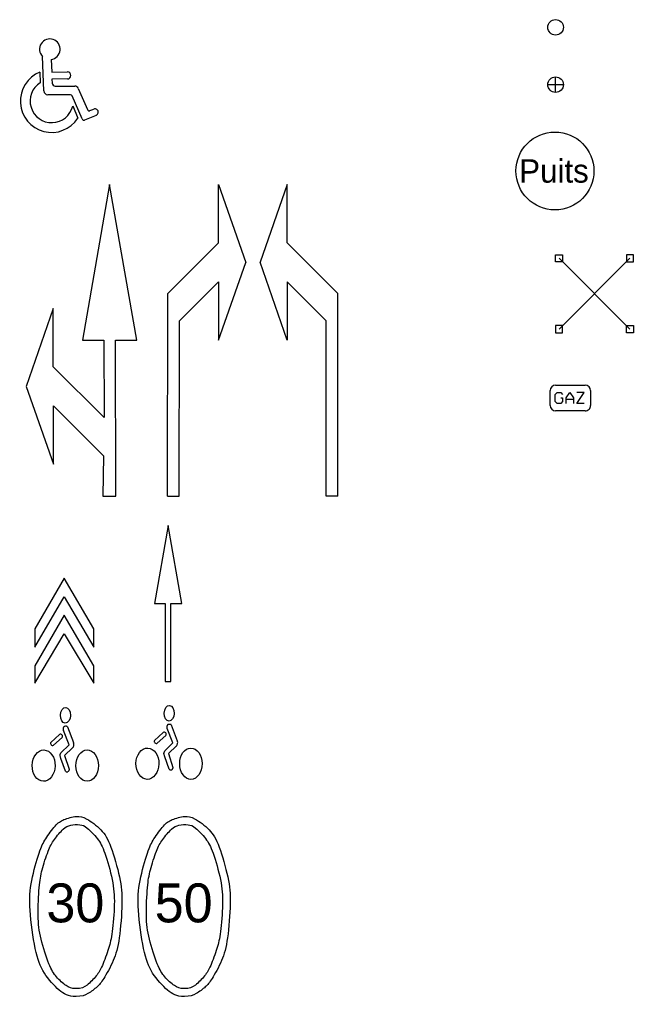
# Model space of a CAD drawing. Extents: x -1.5 to 18.2, y -66.6 to 3.3.
# Drawn here: x 7.93 to 15.81, y -64.82 to -52.28 of the extents above; entities that cross this region are included whole.
import ezdxf

# ---------------------------------------------------------------- set-up
doc = ezdxf.new("R2010")
doc.units = 0
for name, color, linetype in [('SOL_AFFLEUREMENT', 7, 'Continuous'), ('SOL_ELEC_POTEAU', 7, 'Continuous'), ('SOL_MOBILIER_DIVERS', 7, 'Continuous'), ('SOL_PLAQUE_GAZ', 7, 'Continuous'), ('SOL_SIGNALISATION_HORIZONTALE', 7, 'Continuous'), ('SOL_SIGNALISATION_VERTICALE', 7, 'Continuous')]:
    doc.layers.add(name, color=color, linetype=linetype)

# ---------------------------------------------------------------- blocks, each defined once
blk = doc.blocks.new('SYMBOLE_PMR')
for p, q in [((-0.048, 0.492), (-0.065, 0.934)), ((0.047, 0.896), (0.053, 0.734)), ((-0.099, 0.735), (-0.093, 0.598)), ((0.053, 0.734), (0.254, 0.736)), ((0.255, 0.646), (0.057, 0.644)), ((0.057, 0.644), (0.059, 0.593)), ((0.099, 0.554), (0.349, 0.554)), ((0.395, 0.524), (0.511, 0.252)), ((0.293, 0.444), (0.002, 0.444)), ((0.443, 0.132), (0.316, 0.429)), ((0.323, 0.299), (0.39, 0.143)), ((0.543, 0.239), (0.592, 0.258)), ((0.624, 0.179), (0.475, 0.119))]:
    blk.add_line(p, q)
for centre, radius, start, end in [((0.029, 1.028), 0.132, 277.5864, 224.7546), ((0.053, 0.362), 0.402, 112.1232, 326.8956), ((0.254, 0.691), 0.045, 270.3, 90.3), ((0.053, 0.362), 0.277, 121.8325, 346.8056), ((0.099, 0.594), 0.04, 182.1973, 270), ((0.349, 0.504), 0.05, 23.1986, 90), ((0.002, 0.494), 0.05, 182.1973, 270), ((0.293, 0.419), 0.025, 23.1986, 90), ((0.534, 0.262), 0.025, 203.1986, 291.9218), ((0.608, 0.219), 0.0428, 291.9212, 111.9218), ((0.466, 0.142), 0.025, 203.1986, 291.9218)]:
    blk.add_arc(centre, radius, start, end)
blk = doc.blocks.new('REPERE_ARCHEOLOGIQUE')
blk.add_circle((0, 0), 0.1)
blk = doc.blocks.new('CLOU_DE_CHAUSSEE')
for p, q in [((-0.1, 0), (0.1, 0)), ((0, -0.1), (0, 0.1))]:
    blk.add_line(p, q)
blk.add_circle((0, 0), 0.1)
blk = doc.blocks.new('PYLONE_ELECTRIQUE')
for points in [[(0, 1), (0.091, 1), (0.091, 0.909), (0, 0.909)], [(0.909, 0.909), (1, 0.909), (1, 1), (0.909, 1)], [(0.091, 0.091), (0, 0.091), (0, 0), (0.091, 0)], [(0.909, 0.091), (1, 0.091), (1, 0), (0.909, 0)]]:
    blk.add_lwpolyline(points, close=True)
for points in [[(0.955, 0.045), (0.045, 0.955)], [(0.045, 0.045), (0.955, 0.955)]]:
    blk.add_lwpolyline(points)
blk = doc.blocks.new('PLAQUE_GAZ')
for p, q in [((-0.07, 0.07), (-0.07, 0.26)), ((0, 0.33), (0.38, 0.33)), ((0.45, 0.26), (0.45, 0.07)), ((0.38, 0), (0, 0))]:
    blk.add_line(p, q)
for points in [[(0.068, 0.166), (0.091, 0.166), (0.091, 0.119), (0.068, 0.095), (0.021, 0.095), (-0.003, 0.119), (-0.003, 0.211), (0.021, 0.234), (0.068, 0.234), (0.091, 0.211)], [(0.136, 0.095), (0.136, 0.166), (0.183, 0.234), (0.23, 0.166), (0.23, 0.095)], [(0.23, 0.143), (0.136, 0.143)], [(0.369, 0.095), (0.275, 0.095), (0.369, 0.234), (0.275, 0.234)]]:
    blk.add_lwpolyline(points)
for centre, start, end in [((0, 0.26), 90, 180), ((0.38, 0.26), 0.0424, 90), ((0, 0.07), 180.0424, 270), ((0.38, 0.07), 270, 0.0424)]:
    blk.add_arc(centre, 0.07, start, end)
blk = doc.blocks.new('PUITS')
blk.add_circle((0, 0), 0.5)
blk.add_text('Puits', height=0.3).set_placement((-0.458, -0.15))
blk = doc.blocks.new('SYMBOLE_FLECHE_DROIT_GAUCHE')
for p, q in [((0, 4), (-0.346, 1.999)), ((0.354, 2.001), (0, 4)), ((-0.722, 2.409), (-1.069, 1.408)), ((-0.72, 1.659), (-0.722, 2.409)), ((-0.346, 1.999), (-0.071, 2)), ((-0.071, 2), (-0.069, 1.01)), ((0.079, 2), (0.354, 2.001)), ((0.084, 0), (0.079, 2)), ((-0.069, 1.01), (-0.72, 1.659)), ((-1.069, 1.408), (-0.717, 0.409)), ((-0.717, 0.409), (-0.719, 1.159)), ((-0.719, 1.159), (-0.076, 0.518)), ((-0.076, 0.518), (-0.084, 0)), ((-0.084, 0), (0.084, 0))]:
    blk.add_line(p, q)
blk = doc.blocks.new('SYMBOLE_FLECHE_DROITE')
for p, q in [((0.579, 3.249), (0.58, 3.999)), ((0.58, 3.999), (0.929, 2.999)), ((-0.072, 2.6), (0.579, 3.249)), ((0.577, 1.999), (0.929, 2.999)), ((0.078, 2.25), (0.578, 2.749)), ((0.578, 2.749), (0.577, 1.999)), ((-0.075, 0), (-0.072, 2.6)), ((0.075, 0), (0.078, 2.25)), ((-0.075, 0), (0.075, 0))]:
    blk.add_line(p, q)
blk = doc.blocks.new('SYMBOLE_FLECHE_GAUCHE')
for p, q in [((-0.575, 4), (-0.925, 3)), ((-0.575, 3.25), (-0.575, 4)), ((0.075, 2.6), (-0.575, 3.25)), ((-0.575, 2), (-0.925, 3)), ((-0.075, 2.25), (-0.575, 2.75)), ((-0.575, 2.75), (-0.575, 2)), ((0.075, 0), (0.075, 2.6)), ((-0.075, 0), (-0.075, 2.25)), ((0.075, 0), (-0.075, 0))]:
    blk.add_line(p, q)
blk = doc.blocks.new('SYMBOLE_VELO_CHEVRON')
for p, q in [((-0.016, 2.103), (-0.396, 1.453)), ((0.364, 1.453), (-0.016, 2.103)), ((-0.396, 1.215), (-0.016, 1.865)), ((-0.016, 1.865), (0.364, 1.215)), ((-0.016, 1.628), (-0.396, 0.978)), ((0.364, 0.978), (-0.016, 1.628)), ((-0.396, 1.453), (-0.396, 1.215)), ((-0.396, 0.753), (-0.016, 1.39)), ((-0.016, 1.39), (0.364, 0.753)), ((0.364, 1.215), (0.364, 1.453)), ((-0.396, 0.978), (-0.396, 0.753)), ((0.364, 0.753), (0.364, 0.978)), ((0.021, 0.198), (0.024, 0.196)), ((0.047, -0.351), (0.047, -0.355)), ((0.047, -0.355), (0.047, -0.359))]:
    blk.add_line(p, q)
for points in [[(-0.059, -0.139), (0.047, -0.036), (-0.028, 0.149)], [(0.024, 0.196), (0.102, -0.009)], [(-0.079, 0.097), (-0.189, -0.005)], [(-0.154, -0.04), (-0.043, 0.058)], [(0.091, -0.076), (-0.012, -0.174), (0.047, -0.351)], [(-0.059, -0.214), (-0.071, -0.172), (-0.067, -0.159), (-0.059, -0.139)], [(0, -0.375), (-0.059, -0.214)]]:
    blk.add_lwpolyline(points)
for centre, radius, start, end in [((-0.007, 0.173), 0.0247, 156.3706, 174.6855), ((0.051, 0.168), 0.0823, 174.6855, 186.3402), ((0.002, 0.163), 0.0335, 186.3402, 204.655), ((0.006, 0.168), 0.0381, 141.6325, 156.3706), ((-0.003, 0.175), 0.0275, 123.6901, 141.6325), ((-0.01, 0.186), 0.0139, 98.3659, 123.6901), ((0.006, 0.082), 0.119, 87.151, 98.5527), ((0.011, 0.178), 0.0229, 62.3852, 87.7094), ((-0.066, 0.073), 0.0272, 325.3489, 120.0699), ((-0.168, -0.019), 0.0253, 146.5278, 303.4722), ((0.059, -0.039), 0.0469, 330.8025, 345.3791), ((0.032, -0.045), 0.0785, 20.556, 26.6808), ((0.096, -0.021), 0.0104, 3.6619, 20.556), ((0.057, -0.039), 0.0493, 345.3791, 357.5372), ((-0.087, -0.032), 0.194, 357.5372, 3.6619), ((0.016, -0.363), 0.0206, 217.875, 236.3099), ((0.002, -0.341), 0.0505, 311.0091, 323.1301), ((0.01, -0.348), 0.0397, 323.1301, 336.8014), ((0.037, -0.359), 0.0112, 336.8014, 0), ((0.021, -0.355), 0.03, 236.3099, 251.5651), ((0.015, -0.375), 0.00878, 249.2494, 276.771), ((0.018, -0.353), 0.0306, 266.3225, 281.1007), ((0.016, -0.339), 0.0451, 279.8658, 289.9831), ((0.028, -0.371), 0.0105, 289.9831, 311.0091)]:
    blk.add_arc(centre, radius, start, end)
for centre, major_axis, ratio in [((-0.001, 0.343), (-0.003, -0.101), 0.639876), ((-0.281, -0.304), (-0.004, -0.201), 0.732723), ((0.277, -0.304), (0.001, -0.201), 0.716436)]:
    blk.add_ellipse(centre, major_axis=major_axis, ratio=ratio)
blk.add_ellipse((0.026, -0.018), major_axis=(0, -0.0897), ratio=0.949792, start_param=0.849006, end_param=1.061204)
blk = doc.blocks.new('SYMBOLE_VELO_FLECHE')
for p, q in [((-0.016, 2.753), (-0.191, 1.753)), ((0.159, 1.753), (-0.016, 2.753)), ((-0.191, 1.753), (-0.054, 1.753)), ((-0.054, 1.753), (-0.054, 0.753)), ((0.021, 0.753), (0.021, 1.753)), ((0.021, 1.753), (0.159, 1.753)), ((-0.054, 0.753), (0.021, 0.753)), ((0.021, 0.198), (0.024, 0.196)), ((0.047, -0.351), (0.047, -0.355)), ((0.047, -0.355), (0.047, -0.359))]:
    blk.add_line(p, q)
for points in [[(-0.059, -0.139), (0.047, -0.036), (-0.028, 0.149)], [(0.024, 0.196), (0.102, -0.009)], [(-0.079, 0.097), (-0.189, -0.005)], [(-0.154, -0.04), (-0.043, 0.058)], [(0.091, -0.076), (-0.012, -0.174), (0.047, -0.351)], [(-0.059, -0.214), (-0.071, -0.172), (-0.067, -0.159), (-0.059, -0.139)], [(0, -0.375), (-0.059, -0.214)]]:
    blk.add_lwpolyline(points)
for centre, radius, start, end in [((-0.007, 0.173), 0.0247, 156.3706, 174.6855), ((0.051, 0.168), 0.0823, 174.6855, 186.3402), ((0.002, 0.163), 0.0335, 186.3402, 204.655), ((0.006, 0.168), 0.0381, 141.6325, 156.3706), ((-0.003, 0.175), 0.0275, 123.6901, 141.6325), ((-0.01, 0.186), 0.0139, 98.3659, 123.6901), ((0.006, 0.082), 0.119, 87.151, 98.5527), ((0.011, 0.178), 0.0229, 62.3852, 87.7094), ((-0.066, 0.073), 0.0272, 325.3489, 120.0699), ((-0.168, -0.019), 0.0253, 146.5278, 303.4722), ((0.059, -0.039), 0.0469, 330.8025, 345.3791), ((0.032, -0.045), 0.0785, 20.556, 26.6808), ((0.096, -0.021), 0.0104, 3.6619, 20.556), ((0.057, -0.039), 0.0493, 345.3791, 357.5372), ((-0.087, -0.032), 0.194, 357.5372, 3.6619), ((0.016, -0.363), 0.0206, 217.875, 236.3099), ((0.002, -0.341), 0.0505, 311.0091, 323.1301), ((0.01, -0.348), 0.0397, 323.1301, 336.8014), ((0.037, -0.359), 0.0112, 336.8014, 0), ((0.021, -0.355), 0.03, 236.3099, 251.5651), ((0.015, -0.375), 0.00878, 249.2494, 276.771), ((0.018, -0.353), 0.0306, 266.3225, 281.1007), ((0.016, -0.339), 0.0451, 279.8658, 289.9831), ((0.028, -0.371), 0.0105, 289.9831, 311.0091)]:
    blk.add_arc(centre, radius, start, end)
for centre, major_axis, ratio in [((-0.001, 0.343), (-0.003, -0.101), 0.639876), ((-0.281, -0.304), (-0.004, -0.201), 0.732723), ((0.277, -0.304), (0.001, -0.201), 0.716436)]:
    blk.add_ellipse(centre, major_axis=major_axis, ratio=ratio)
blk.add_ellipse((0.026, -0.018), major_axis=(0, -0.0897), ratio=0.949792, start_param=0.849006, end_param=1.061204)
blk = doc.blocks.new('SYMBOLE_ZONE_TRENTE')
for points in [[(0.003, -1.161), (0.078, -1.161), (0.152, -1.133), (0.284, -1.034), (0.343, -0.962), (0.494, -0.698), (0.561, -0.454), (0.603, 0.068), (0.578, 0.343), (0.445, 0.801), (0.339, 0.984), (0.12, 1.139), (0.02, 1.161), (-0.169, 1.113), (-0.256, 1.046), (-0.401, 0.852), (-0.461, 0.724), (-0.582, 0.314), (-0.603, -0.012), (-0.524, -0.602), (-0.425, -0.863), (-0.202, -1.107), (-0.101, -1.161), (0.003, -1.161)], [(0.003, -1.061), (0.07, -1.061), (0.139, -1.03), (0.273, -0.893), (0.335, -0.788), (0.431, -0.527), (0.465, -0.372), (0.504, 0.045), (0.481, 0.318), (0.366, 0.719), (0.288, 0.864), (0.133, 1.02), (0.062, 1.05), (-0.077, 1.043), (-0.15, 1.005), (-0.288, 0.848), (-0.351, 0.73), (-0.442, 0.445), (-0.472, 0.278), (-0.493, -0.146), (-0.461, -0.407), (-0.337, -0.781), (-0.259, -0.911), (-0.116, -1.037), (-0.056, -1.061), (0.003, -1.061)]]:
    blk.add_open_spline(points, degree=3)
blk.add_text('30', height=0.5).set_placement((-0.378, -0.21))
blk = doc.blocks.new('SYMBOLE_ZONE_CINQUANTE')
for points in [[(0.003, -1.161), (0.078, -1.161), (0.152, -1.133), (0.284, -1.034), (0.343, -0.962), (0.494, -0.698), (0.561, -0.454), (0.603, 0.068), (0.578, 0.343), (0.445, 0.801), (0.339, 0.984), (0.12, 1.139), (0.02, 1.161), (-0.169, 1.113), (-0.256, 1.046), (-0.401, 0.852), (-0.461, 0.724), (-0.582, 0.314), (-0.603, -0.012), (-0.524, -0.602), (-0.425, -0.863), (-0.202, -1.107), (-0.101, -1.161), (0.003, -1.161)], [(0.003, -1.061), (0.07, -1.061), (0.139, -1.03), (0.273, -0.893), (0.335, -0.788), (0.431, -0.527), (0.465, -0.372), (0.504, 0.045), (0.481, 0.318), (0.366, 0.719), (0.288, 0.864), (0.133, 1.02), (0.062, 1.05), (-0.077, 1.043), (-0.15, 1.005), (-0.288, 0.848), (-0.351, 0.73), (-0.442, 0.445), (-0.472, 0.278), (-0.493, -0.146), (-0.461, -0.407), (-0.337, -0.781), (-0.259, -0.911), (-0.116, -1.037), (-0.056, -1.061), (0.003, -1.061)]]:
    blk.add_open_spline(points, degree=3)
blk.add_text('50', height=0.5).set_placement((-0.378, -0.21))

msp = doc.modelspace()

# ---------------------------------------------------------------- block references
at = {"layer": 'SOL_AFFLEUREMENT'}
msp.add_blockref('CLOU_DE_CHAUSSEE', (14.805, -53.119), dxfattribs=at)
at = {"layer": 'SOL_ELEC_POTEAU'}
msp.add_blockref('PYLONE_ELECTRIQUE', (14.805, -56.303), dxfattribs=at)
at = {"layer": 'SOL_MOBILIER_DIVERS'}
msp.add_blockref('REPERE_ARCHEOLOGIQUE', (14.805, -52.383), dxfattribs=at)
at = {"layer": 'SOL_PLAQUE_GAZ'}
msp.add_blockref('PLAQUE_GAZ', (14.805, -57.306), dxfattribs=at)
at = {"layer": 'SOL_SIGNALISATION_HORIZONTALE'}
for name, p in [('SYMBOLE_PMR', (8.285, -53.692)), ('SYMBOLE_FLECHE_DROIT_GAUCHE', (9.079, -58.4)), ('SYMBOLE_FLECHE_DROITE', (9.9, -58.4)), ('SYMBOLE_FLECHE_GAUCHE', (11.937, -58.4)), ('SYMBOLE_VELO_FLECHE', (9.848, -61.532)), ('SYMBOLE_VELO_CHEVRON', (8.516, -61.557)), ('SYMBOLE_ZONE_TRENTE', (8.648, -63.663)), ('SYMBOLE_ZONE_CINQUANTE', (10.038, -63.663))]:
    msp.add_blockref(name, p, dxfattribs=at)
at = {"layer": 'SOL_SIGNALISATION_VERTICALE'}
msp.add_blockref('PUITS', (14.797, -54.227), dxfattribs=at)

doc.saveas('drawing.dxf')
